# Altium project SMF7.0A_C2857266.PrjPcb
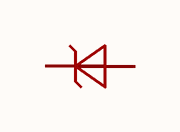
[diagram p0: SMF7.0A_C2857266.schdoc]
1 sheet, 1 parts. Net scope: global (net labels, ports and power ports of the same name join across sheets).

## Sheet SMF7.0A_C2857266.schdoc
size 127 x 101 mm

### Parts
D?  smf7.0a_c2857266  [SOD-123FL_L2.7-W1.8-LS3.7-RD]  (value not drawn)

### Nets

Not connected (* = marked no-connect by the designer): D? 1 2

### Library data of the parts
D? = smf7.0a_c2857266: 极性:单向;反向截止电压(Vrwm):7V;钳位电压:12V;峰值脉冲电流(Ipp):16.7A;峰值脉冲功率(Ppp):200W;击穿电压(VBR):7.8V;; Manufacturer: JSMSEMI(杰盛微); AddInBom: yes; ModelId: 86f9151e155e4fe2af0c4f2e0a80302e; ModelName: SOD-123FL_L2.8-W1.8-H1.1-LS3.6; ModelTransform: 141.732,70.866,0,180,0,0,0,0,0; Polarity: 单向; Reverse Stand-Off Voltage (Vrwm): 7V; Clamping Voltage: 12V; Peak Pulse Current (Ipp): 16.7A; Peak Pulse Power Dissipation (Ppp): 200W; Voltage - Breakdown: 7.8V; Reverse Leakage Current (Ir): 30uA; Number of Channels: 单路; Type: TVS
